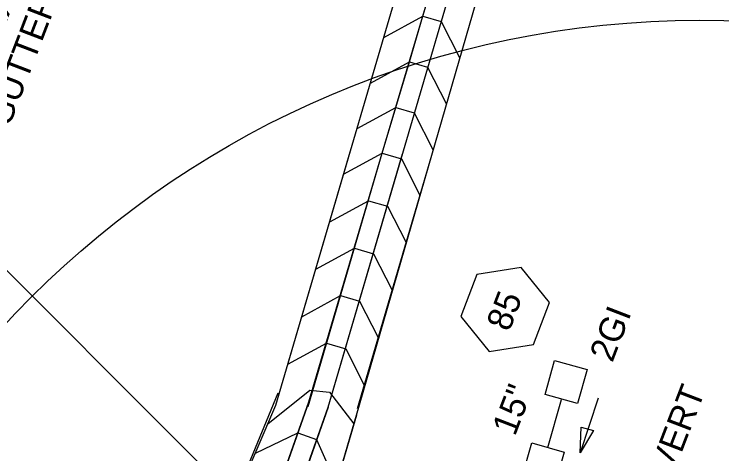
# Model space of a CAD drawing. Extents: x 2384780 to 2405432, y 547869 to 573706.
# Drawn here: x 2400102.1 to 2400242.9, y 562711 to 562798.4 of the extents above; entities that cross this region are included whole.
import ezdxf

# ---------------------------------------------------------------- set-up
doc = ezdxf.new("R2010")
doc.units = 0
for name, color, linetype in [('Old_Level_1', 7, 'Continuous'), ('Old_Level_18', 7, 'Continuous'), ('Old_Level_20', 7, 'Continuous'), ('Old_Level_48', 7, 'Continuous'), ('Old_Level_5', 7, 'Continuous'), ('Old_Level_63', 7, 'Continuous'), ('Old_Level_9', 7, 'Continuous'), ('Prop Drainage Box Number Symbol CELL', 7, 'Continuous')]:
    doc.layers.add(name, color=color, linetype=linetype)

msp = doc.modelspace()

# ---------------------------------------------------------------- linework, layer by layer
at = {"layer": 'Old_Level_1'}
msp.add_line((2400208.28, 562712.27), (2400210.97, 562721.8), dxfattribs=at)
msp.add_lwpolyline([(2400203.16, 562706.41), (2400205.06, 562713.18), (2400211.51, 562711.36), (2400209.61, 562704.6)], close=True, dxfattribs=at)
at = {"layer": 'Old_Level_18'}
for points in [[(2400175.36, 562770.79), (2400188.78, 562816.21)], [(2400175.36, 562770.79), (2400178.04, 562779.88), (2400180.73, 562788.96), (2400183.41, 562798.04), (2400186.1, 562807.13), (2400188.78, 562816.21)], [(2400179.08, 562769.7), (2400192.42, 562815.23)], [(2400109.1, 562609.09), (2400135.79, 562677.71), (2400154.21, 562720.68), (2400180.96, 562811.96)], [(2400140.62, 562619.32), (2400156.48, 562671.67), (2400170.2, 562718.7), (2400196.06, 562808)], [(2400175.65, 562793.82), (2400183.41, 562798.04), (2400187.05, 562796.97), (2400190.76, 562789.7)], [(2400172.99, 562784.75), (2400180.73, 562788.96), (2400184.37, 562787.88), (2400188.11, 562780.55)], [(2400170.33, 562775.68), (2400178.04, 562779.88), (2400181.68, 562778.8), (2400185.46, 562771.39)], [(2400121.96, 562613.27), (2400144.45, 562675.18), (2400160.75, 562721.35), (2400175.36, 562770.79)], [(2400167.67, 562766.59), (2400175.36, 562770.79), (2400179.14, 562769.68), (2400182.85, 562762.46)], [(2400126.78, 562614.83), (2400148.29, 562674.06), (2400164.6, 562720.27), (2400179.08, 562769.7)], [(2400164.9, 562757.14), (2400172.59, 562761.35), (2400176.38, 562760.24), (2400180.08, 562753.02)], [(2400162.13, 562747.7), (2400169.82, 562751.9), (2400173.61, 562750.79), (2400177.31, 562743.57)], [(2400159.36, 562738.25), (2400167.06, 562742.46), (2400170.84, 562741.35), (2400174.55, 562734.13)], [(2400156.6, 562728.81), (2400164.29, 562733.01), (2400168.07, 562731.9), (2400171.78, 562724.68)], [(2400152.61, 562716.94), (2400160.94, 562723.68), (2400164.86, 562723.27), (2400169.7, 562716.96)], [(2400150.12, 562711.12), (2400158.56, 562715.16), (2400162.28, 562713.84), (2400166.21, 562705.02)]]:
    msp.add_lwpolyline(points, dxfattribs=at)
at = {"layer": 'Old_Level_48'}
for p, q in [((2400154.21, 562720.68), (2400168.97, 562771.04)), ((2400160.6, 562720.43), (2400175.36, 562770.79)), ((2400164.6, 562720.27), (2400179.36, 562770.64)), ((2400170.42, 562720.04), (2400185.18, 562770.41)), ((2400154.59, 562723.08), (2400135.79, 562677.71)), ((2400154.59, 562723.08), (2400135.79, 562677.71)), ((2400160.75, 562721.35), (2400144.45, 562675.18)), ((2400160.75, 562721.35), (2400144.45, 562675.18)), ((2400164.6, 562720.27), (2400148.29, 562674.06)), ((2400164.6, 562720.27), (2400148.29, 562674.06)), ((2400170.2, 562718.7), (2400156.48, 562671.67)), ((2400170.2, 562718.7), (2400156.48, 562671.67))]:
    msp.add_line(p, q, dxfattribs=at)
at = {"layer": 'Old_Level_5'}
msp.add_line((2400218.25, 562722.09), (2400214.69, 562711.18), dxfattribs=at)
msp.add_lwpolyline([(2400217.32, 562715.62), (2400214.69, 562711.18), (2400214.92, 562716.33)], close=True, dxfattribs=at)
at = {"layer": 'Old_Level_63'}
msp.add_lwpolyline([(2400238.44, 562609.29), (2399506.43, 563343.62), (2399267.9, 563319.69)], dxfattribs=at)
msp.add_circle((2400238.44, 562609.29), 187.94, dxfattribs=at)
at = {"layer": 'Old_Level_9'}
msp.add_lwpolyline([(2400207.73, 562722.78), (2400209.6, 562729.55), (2400216.06, 562727.77), (2400214.19, 562721)], close=True, dxfattribs=at)
at = {"layer": 'Prop Drainage Box Number Symbol CELL'}
msp.add_lwpolyline([(2400203, 562748.06), (2400194.16, 562746.66), (2400190.95, 562738.3), (2400196.58, 562731.35), (2400205.42, 562732.75), (2400208.63, 562741.1)], close=True, dxfattribs=at)

# ---------------------------------------------------------------- texts
at = {"layer": 'Old_Level_1'}
msp.add_text('TIE INTO CULVERT', height=5, rotation=69, dxfattribs=at).set_placement((2400217.64, 562666.22))
at = {"layer": 'Old_Level_20'}
msp.add_text('15"', height=5, rotation=68.9999, dxfattribs=at).set_placement((2400201.73, 562714.35))
at = {"layer": 'Old_Level_5'}
for s, p in [('GUTTER STA. 156+00 LT', (2400101.1, 562775.74)), ('END EXPRESSWAY', (2400093.64, 562778.61)), ('2GI', (2400221.1, 562729.01))]:
    msp.add_text(s, height=5, rotation=68.9999, dxfattribs=at).set_placement(p)
at = {"layer": 'Prop Drainage Box Number Symbol CELL'}
msp.add_text('85', height=5, rotation=68.9999, dxfattribs=at).set_placement((2400200.58, 562735.13))

doc.saveas('drawing.dxf')
